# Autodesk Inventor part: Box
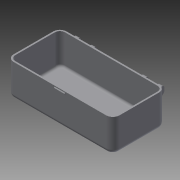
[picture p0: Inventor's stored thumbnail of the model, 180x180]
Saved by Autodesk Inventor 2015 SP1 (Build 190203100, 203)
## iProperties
Created: 2014-11
Part Number: Box
Material: Generisch
Document SubType Name: Modeling
Designer: Watson
Density: 1 g/cm^3
Appearance: Vorgabe
Author: Watson
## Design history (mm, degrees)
sketch "Skizze1"
  geometry: L1 (-40, -20)-(40, -20); L2 (40, -20)-(40, 20); L3 (40, 20)-(-40, 20); L4 (-40, 20)-(-40, -20); L5 (-40, -20)-(40, 20); L6 (40, -20)-(-40, 20); 1 further point
  constraints: 12 end point, 2 midpoint, 2 parallel, 1 horizontal, 1 perpendicular
  dimensions: "d0" = 40 distance of L1.end L2.end; "d1" = 80 distance of L2.end L3.end
extrude "Extrusion1" new body sketch "Skizze1" stored distance "d2" = 24.5; taper "d3" = 0 deg
fillet "Rundung1" dims "d4" = 5
fillet "Rundung3" dims "d20" = 3
feature "Wandung1" dims "d21" = 1.2
workplane "Arbeitsebene1"
sketch "Skizze2"
  geometry: L1 (0, 35.2)-(0, -29.2); L2 (35, 20)-(-35, 20); L3 (18, 20)-(33, 20); L4 (33, 20)-(33, 26); L5 (33, 26)-(18, 26); L6 (18, 26)-(18, 20); 1 further point
  constraints: 12 end point, 2 parallel, 1 horizontal, 1 perpendicular, 1 point on line
  dimensions: "d5" = 15 distance of L4.end L5.end; "d6" = 6 distance of L3.end L4.end; "d7" = 18 distance between parallel lines of L6 L1
extrude "Extrusion2" join sketch "Skizze2" distance "d8" = 4.5; taper "d9" = 0 deg
sketch "Skizze3"
  geometry: L1 (18, 26)-(18, 20) reference; L2 (33, 26)-(18, 26) reference; L3 (33, 20)-(33, 26) reference; L4 (21, 26)-(30, 26); L5 (30, 26)-(30, 20); L6 (30, 20)-(21, 20); L7 (21, 20)-(21, 26); 1 further point
  constraints: 8 end point, 2 parallel, 1 horizontal, 1 horizontal alignment, 1 perpendicular, 1 point on line
  dimensions: "d10" = 3 distance between parallel lines of L1 L7; "d11" = 3 distance between parallel lines of L3 L5
extrude "Extrusion3" cut sketch "Skizze3" stored distance "d12" = 6; taper "d13" = 0 deg
sketch "Skizze4"
  geometry: L1 (0, 6)-(0, 0) reference; L2 (0, 6)-(4.5, 6) reference; C1 r 1.5 at (3, 4); 1 further point
  constraints: 1 centre point
  dimensions: "d14" = 3 distance from line of C1.centre L1; "d15" = 2 distance from line of L2 C1.centre; "d16" = 3 diameter of C1
extrude "Extrusion4" join sketch "Skizze4" stored distance "d17" = 6; taper "d18" = 0 deg
sketch "Skizze9"
  geometry: L1 (4.5, 6)-(4.5, 0) reference; L2 (17.5, 0)-(-4, 0) reference; L3 (4.5, 6)-(10.5, 0); 1 further point
  constraints: 2 end point, 1 point on line
  dimensions: "d43" = 45 deg angle of L2 L3
extrude "Extrusion9" join sketch "Skizze9" stored distance "d44" = 5; taper "d45" = 0 deg
sketch "Skizze10"
  geometry: L1 (-4.5, 6)-(-10.5, 0) reference; L2 (4, -5)-(-17.5, -5) reference; L3 (-4.5, 0)-(-4.5, 6) reference; L4 (-10.5, 0)-(0, 0) reference; L5 (-17.5, 0)-(4, 0) reference; L6 (4, 0)-(-17.5, 0) reference; L7 (0, 0)-(-4.5, 0) reference; L8 (0, 0)-(-4.5, 0) reference; L9 (0, 0)-(-10.5, 0) reference; L10 (-4.5, 0)-(-4.5, 6); L11 (-4.5, 6)-(-10.5, 0); L12 (-10.5, 0)-(-4.5, 0); 1 further point
  constraints: 6 end point, 2 collinear, 1 vertical, 1 other
extrude "Extrusion10" join sketch "Skizze10" stored distance "d46" = 5; taper "d47" = 0 deg
fillet "Rundung2" dims "d19" = 2
mirror "Spiegeln1"
fillet "Rundung5" dims "d23" = 1
fillet "Rundung8" dims "d48" = 1
sketch "Skizze11"
  geometry: L1 (-20, 12.25)-(-20, -9.25) reference; L2 (-20, -9.25)-(-20, 12.25) reference; L3 (18.8, 12.25)-(15, 12.25) reference; L4 (15, 12.25)-(-15, 12.25) reference; L5 (-15, 12.25)-(-18.8, 12.25) reference; L6 (-18.8, 12.25)-(-15, 12.25) reference; L7 (-15, 12.25)-(15, 12.25) reference; L8 (15, 12.25)-(18.8, 12.25) reference; L9 (-20, 12.25)-(-15, 12.25) reference; L10 (-15, 12.25)-(-20, 12.25) reference; L11 (-15, 12.25)-(15, 12.25) reference; L12 (20, 12.25)-(15, 12.25) reference; L13 (15, 12.25)-(20, 12.25) reference; L14 (15, 12.25)-(-15, 12.25) reference; L15 (-20, 11.55)-(-20.5, 11.05); L16 (-20.5, 11.05)-(-20.5, 10.45); L17 (-20.5, 10.45)-(-20, 9.95); 1 further point
  constraints: 6 end point, 2 point on line, 1 vertical
  dimensions: "d50" = 45 deg angle of L1 L17; "d51" = 0.5 distance between parallel lines of L1 L16; "d52" = 45 deg angle of L1 L15; "d53" = 1.8 distance from line of L16.end L9; "d54" = 0.6 distance of L15.end L16.end
extrude "Extrusion11" join sketch "Skizze11" stored distance "d55" = 8; taper "d56" = 0 deg
node "Volumenkörper1"
node "Projizierte Kontur2"
node "Projizierte Kontur3"
node "Projizierte Kontur4"
other parameters: "d49" = -4
